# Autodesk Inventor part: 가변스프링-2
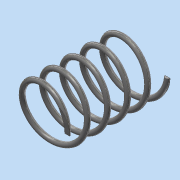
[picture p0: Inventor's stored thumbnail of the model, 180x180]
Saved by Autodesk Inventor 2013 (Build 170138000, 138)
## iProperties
Created: 2020-07
Part Number: 가변스프링-2
Material: 스테인리스강
Document SubType Name: Modeling
Designer: dgall
Density: 8.08 g/cm^3
Mass: 8.67973 g
Surface Area: 21.7273 cm^2
Volume: 1.07422 cm^3
Author: dgall
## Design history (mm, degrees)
sketch "스케치1"
  geometry: L1 (0, 0)-(0, 40.295); L2 (0, 40.295)-(11, 40.295); L3 (0, 0)-(11, 0); C1 r 1 at (11, 0)
  constraints: 6 end point, 2 parallel, 1 centre point, 1 coincident, 1 perpendicular, 1 vertical
  dimensions: "d0" = 40.2955 distance of L1.start L1.end (derived); "d1" = 22 diameter of L2.end L1; "d2" = 2 diameter of C1
feature "코일1" pitch "d3" = 10; turns "d5" = 5; dims "d4" = 40.2955 (= d0), "d6" = 0, angle "d7" = 90 deg, angle "d8" = 90 deg, "d9" = 0, "d10" = 0
node "작업 평면1"
node "작업 평면2"
feature "분할1"
feature "분할2"
node "솔리드1"
